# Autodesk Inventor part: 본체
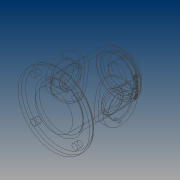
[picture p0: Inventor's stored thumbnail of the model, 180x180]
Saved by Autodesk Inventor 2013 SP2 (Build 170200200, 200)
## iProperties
Created: 2014-12
Part Number: 본체
Material: 알루미늄 6061
Document SubType Name: Modeling
Designer: CADB303
Density: 2.71 g/cm^3
Author: CADB303
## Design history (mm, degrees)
sketch "스케치1"
  geometry: L1 (0, 53)-(0, -53); L2 (0, -53)-(-52.5, -53); L3 (-52.5, -53)-(-52.5, -45); L4 (-52.5, -45)-(-32.5, -45); L5 (-32.5, -45)-(-32.5, 45); L6 (-32.5, 45)-(-22.5, 45); L7 (-22.5, 45)-(-22.5, 53); L8 (-22.5, 53)-(0, 53); L9 (0, 40)-(-27.5, 40); L10 (-27.5, 40)-(-27.5, -53); 2 further points
  constraints: 20 end point, 6 parallel, 3 perpendicular, 2 point on line, 1 coincident, 1 midpoint, 1 vertical
  dimensions: "d0" = 106 distance of L1.start L1.end; "d2" = 98 distance between parallel lines of L6 L2; "d3" = 93 distance between parallel lines of L9 L2; "d4" = 45 diameter of L7.end L1; "d5" = 65 diameter of L5 L1; "d6" = 55 diameter of L10 L1; "d7" = 8 distance between parallel lines of L4 L2; "d8" = 105 diameter of L3 L1
revolve "회전1" sketch "스케치1" stored, may be unused: angle "d9" = 90 deg
node "작업 평면1"
sketch "스케치2"
  geometry: L1 (-53, -52.5)-(-53, 52.5) reference; C1 r 25 at (2, 0); 1 further point
  constraints: 1 centre point, 1 horizontal alignment
  dimensions: "d15" = 50 diameter of C1; "d16" = 55 distance from line of C1.centre L1
extrude "돌출1" join sketch "스케치2" stored distance "d17" = 10; taper "d18" = 0 deg
hole "구멍1" diameter "d21" = 25; stored, may be unused: countersink angle "d25" = 90 deg, drill point angle "d27" = 0 deg; dims "d19" = 10, "d20" = 10, "d22" = 6, "d23" = 32, "d24" = 12, "d26" = 20
hole "구멍2" diameter "d30" = 27; stored, may be unused: countersink angle "d34" = 90 deg, drill point angle "d36" = 0 deg; dims "d28" = 10, "d29" = 10, "d31" = 6, "d32" = 32, "d33" = 12, "d35" = 20
sketch "스케치3"
  geometry: L1 (0, 0)-(30.406, 30.406); L2 (0, 0)-(43, 0); 1 further point
  constraints: 4 end point, 1 coincident, 1 equal length, 1 horizontal
  dimensions: "d37" = 43 distance of L1.start L1.end; "d38" = 45 deg angle of L2 L1
hole "구멍3" sketch "스케치3" at (30.406, 30.406) diameter "d39" = 8; stored, may be unused: countersink angle "d43" = 90 deg, drill point angle "d45" = 0 deg; dims "d40" = 6, "d41" = 32, "d42" = 12, "d44" = 8
sketch "스케치4"
  geometry: 2 further points
  constraints: 1 vertical alignment
  dimensions: "d49" = 17.5 distance of point (0, 17.5) point (0, 0)
hole "구멍4" sketch "스케치4" at (0, 17.5) diameter "d50" = 2.459; stored, may be unused: countersink angle "d54" = 90 deg, drill point angle "d56" = 0 deg; dims "d51" = 6, "d52" = 32, "d53" = 12, "d55" = 8
sketch "스케치5"
  geometry: C1 r 12.5 at (0, 0) reference; 2 further points
  constraints: 1 vertical alignment
  dimensions: "d60" = 20.5 distance of point (0, 20.5) C1.centre
hole "구멍5" sketch "스케치5" at (0, 20.5) diameter "d61" = 3; stored, may be unused: countersink angle "d65" = 90 deg, drill point angle "d67" = 118 deg; dims "d62" = 6, "d63" = 4, "d64" = 2, "d66" = 8
chamfer "모따기1" distance "d72" = 1; stored, may be unused: second distance "d73" = 2, angle "d74" = 45 deg
node "작업 평면3"
sketch "스케치7"
  geometry: L1 (53, -22.5)-(53, 22.5) reference; L2 (45, -32.5)-(45, 32.5) reference; 3 further points
  constraints: 1 horizontal alignment, 1 midpoint, 1 other
  dimensions: "d78" = 9 distance from line of point (36, 0) L2
feature "엠보싱1" sketch "스케치7" dims "d0" = 106, "d2" = 98, "d3" = 93, "d4" = 45, "d5" = 65, "d6" = 55, "d7" = 8, "d8" = 105, "d23" = 32, "d79" = 1, "d80" = 0
fillet "모깎기2" dims "d81" = 3
fillet "모깎기3" dims "d82" = 0.3
node "솔리드1"
pattern_circular "원형 패턴1" dims angle "d47" = 360 deg
pattern_circular "원형 패턴2" dims angle "d58" = 360 deg
pattern_circular "원형 패턴3" dims angle "d69" = 360 deg
mirror "대칭2"
other parameters: "d10" = 42.5, "d75" = 32.5
